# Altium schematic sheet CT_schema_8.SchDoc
size 274 x 160 mm
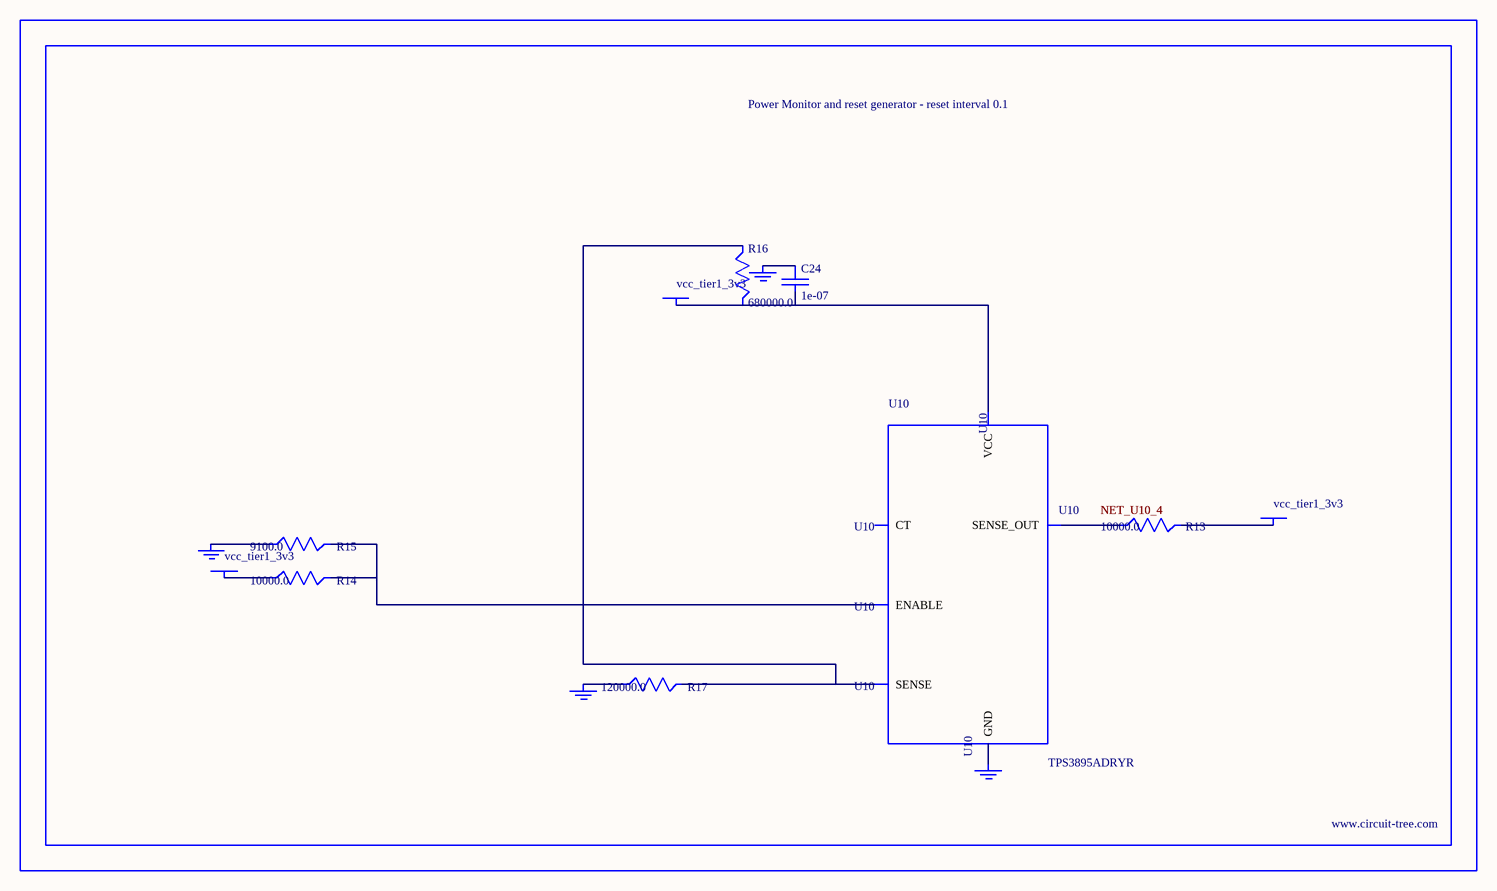
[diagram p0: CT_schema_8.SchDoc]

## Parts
BORDER7  (no value)
C24  1e-07  [C0402]
GND_INSTANCE_7_0  (no value)
GND_INSTANCE_7_1  (no value)
GND_INSTANCE_7_2  (no value)
GND_INSTANCE_7_3  (no value)
POWER_INSTANCE_7_0  vcc_tier1_3v3
POWER_INSTANCE_7_1  vcc_tier1_3v3
POWER_INSTANCE_7_2  vcc_tier1_3v3
R13  10000.0  [R0603]
R14  10000.0  [R0603]
R15  9100.0  [R0603]
R16  680000.0  [R0603]
R17  120000.0  [R0603]
U10  TPS3895ADRYR  [SON-6]

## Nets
NetC24_1: C24.1 GND_INSTANCE_7_2.0(GND)
NetC24_2: C24.2 POWER_INSTANCE_7_2.0(PWR) R16.2 U10.6(VCC)
NetGND_INSTANCE_7_0_0: GND_INSTANCE_7_0.0(GND) R15.1
NetGND_INSTANCE_7_1_0: GND_INSTANCE_7_1.0(GND) R17.1
NetGND_INSTANCE_7_3_0: GND_INSTANCE_7_3.0(GND) U10.2(GND)
NetPOWER_INSTANCE_7_0_0: POWER_INSTANCE_7_0.0(PWR) R14.1
NetPOWER_INSTANCE_7_1_0: POWER_INSTANCE_7_1.0(PWR) R13.2
NetR13_1: R13.1 U10.4(SENSE_OUT)
NetR14_2: R14.2 R15.2 U10.1(ENABLE)
NetR16_1: R16.1 R17.2 U10.3(SENSE)

Not connected (* = marked no-connect by the designer): U10 5(CT)

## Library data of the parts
BORDER7 = BORDER_PAGE7
C24 = C0402C104K3RACTU
GND_INSTANCE_7_0-GND_INSTANCE_7_3 = GND
POWER_INSTANCE_7_0-POWER_INSTANCE_7_2 = PWR
R13 R14 = RC0603JR-0710KL
R15 = RC0603JR-079K1L
R16 = RC0603JR-07680KL
R17 = RC0603JR-07120KL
